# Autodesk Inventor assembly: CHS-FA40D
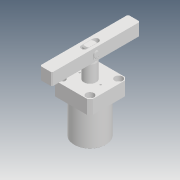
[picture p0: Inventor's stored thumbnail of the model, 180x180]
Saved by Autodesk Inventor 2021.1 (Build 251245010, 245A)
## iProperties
Created: 2019-04
Part Number: CHS-FA40D
Description: STEP AP203
Document SubType Name: Assembly
Designer: user
Title: chs-fa40d_asm.STEP
Revision Number: ÈÎºÎ
Sending System: SolidWorks 2017
Preprocessor: SwSTEP 2.0
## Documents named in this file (6)
- D:\Vault_2016\Projekty\Clamptek\Hydraulic\CHS\CHS-40\Inventor\CHS-FA40D\CHS-FA40D.iam
- D:\Vault_2016\Projekty\Clamptek\Hydraulic\CHS\CHS-40\Inventor\CHS-FA40D\CHS-FA40  BT.ipt
- D:\Vault_2016\Projekty\Clamptek\Hydraulic\CHS\CHS-40\Inventor\CHS-FA40D\XIAO.ipt
- D:\Vault_2016\Projekty\Clamptek\Hydraulic\CHS\CHS-40\Inventor\CHS-FA40D\12ÖáÓÃµ²È¦.ipt
- D:\Vault_2016\Projekty\Clamptek\Hydraulic\CHS\CHS-40\Inventor\CHS-FA40D\CHS-40D-02_1.ipt
- D:\Vault_2016\Projekty\Clamptek\Hydraulic\CHS\CHS-40\Inventor\CHS-FA40D\CHS-40D-01_2.ipt
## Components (6 placed, 6 different names)
1. CHS-FA40  BT_1
2. XIAO_2
3. 12ÖáÓÃµ²È¦_3
4. CHS-40D-02_1_4
5. CHS-40D-01_2_5
6. 12ÖáÓÃµ²È¦_6
